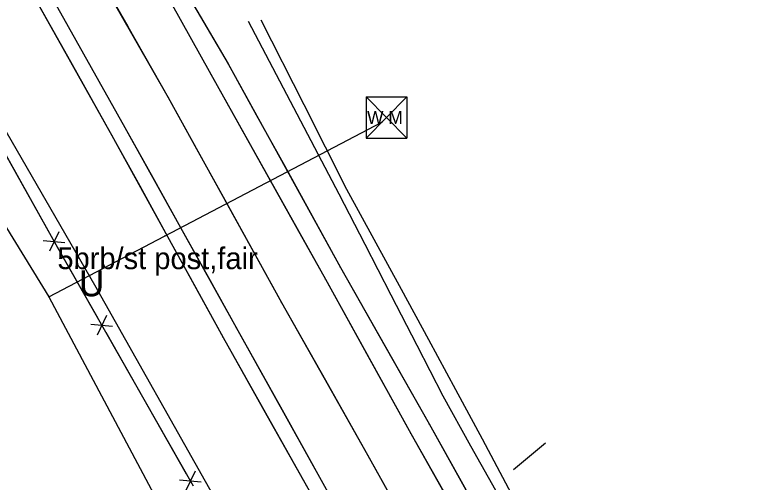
# Model space of a CAD drawing. Extents: x -99999 to 591807, y -99999 to 347168.
# Drawn here: x 589017.5 to 589188.3, y 344083.1 to 344190.7 of the extents above; entities that cross this region are included whole.
import ezdxf

# ---------------------------------------------------------------- set-up
doc = ezdxf.new("R2010")
doc.units = 0
for name, color, linetype in [('S_DITCHLINE', 7, 'Continuous'), ('S_EDGE_PAVEMENT', 7, 'Continuous'), ('S_FENCE', 7, 'Continuous'), ('S_FENCE_ANNOT', 7, 'Continuous'), ('S_MSC_PT_SYM', 7, 'Continuous'), ('S_PAVEMENT_CROWN', 7, 'Continuous'), ('S_RDW_PT_SYM', 7, 'Continuous'), ('S_SHOULDER', 7, 'Continuous'), ('S_UNDERGROUND_CABLE', 7, 'Continuous'), ('S_UTL_PT_SYM', 7, 'Continuous'), ('S_WATER_UTILITIES', 7, 'Continuous')]:
    doc.layers.add(name, color=color, linetype=linetype)

msp = doc.modelspace()

# ---------------------------------------------------------------- linework, layer by layer
at = {"layer": 'S_DITCHLINE'}
for points in [[(589071.18, 344189.2), (589081.62, 344169.35), (589092.05, 344149.49), (589098.03, 344137.86), (589104.01, 344126.23), (589109.98, 344114.6), (589115.96, 344102.97), (589122.36, 344091.49), (589128.76, 344080.01), (589135.52, 344066.08), (589142.28, 344052.16)], [(589074.12, 344189.54), (589083.99, 344170.05), (589093.86, 344150.55), (589100.13, 344139.02), (589106.4, 344127.49), (589112.67, 344115.96), (589118.94, 344104.44), (589125.03, 344093.05), (589131.12, 344081.67), (589138.87, 344067.77), (589146.61, 344053.87)], [(589132.23, 344086.04), (589139.62, 344092.13)]]:
    msp.add_lwpolyline(points, dxfattribs=at)
at = {"layer": 'S_EDGE_PAVEMENT'}
for points in [[(589044.06, 344210.38), (589062.61, 344176.98), (589089.04, 344129.8), (589108.67, 344094.28), (589125.56, 344064.19), (589145.2, 344028.97), (589161.69, 343999.91), (589175.36, 343974.71), (589194.37, 343940.44), (589208.05, 343916.06), (589231.37, 343874.53), (589249.48, 343841.72), (589270.08, 343805.14), (589289.8, 343769.16), (589308.91, 343733.9), (589328.84, 343697.75)], [(589023.86, 344198.7), (589042.88, 344164.72), (589068.45, 344118.72), (589088.8, 344082.18), (589106.8, 344049.99), (589124.92, 344017.73), (589142.03, 343987.05), (589155.39, 343963.21), (589174.41, 343928.82), (589188.27, 343903.72), (589210.34, 343864.33), (589229.44, 343830.56), (589250.2, 343793.38), (589269.11, 343758.95), (589288.96, 343722.64), (589307.86, 343688.02)], [(589023.86, 344198.7), (589033.37, 344181.71), (589042.88, 344164.72), (589049.27, 344153.22), (589055.66, 344141.72), (589062.06, 344130.22), (589068.45, 344118.72), (589078.62, 344100.45), (589088.8, 344082.18), (589097.8, 344066.09), (589106.8, 344049.99), (589115.86, 344033.86), (589124.92, 344017.73), (589133.47, 344002.39), (589142.03, 343987.05), (589148.71, 343975.13), (589155.39, 343963.21)], [(589053.34, 344193.68), (589062.61, 344176.98), (589069.22, 344165.18), (589075.82, 344153.39), (589082.43, 344141.59), (589089.04, 344129.8), (589098.85, 344112.04), (589108.67, 344094.28), (589117.12, 344079.24), (589125.56, 344064.19), (589135.38, 344046.58), (589145.2, 344028.97), (589153.44, 344014.44), (589161.69, 343999.91), (589168.52, 343987.31), (589175.36, 343974.71), (589184.86, 343957.58)]]:
    msp.add_lwpolyline(points, dxfattribs=at)
at = {"layer": 'S_FENCE'}
for p, q in [((588991.55, 344201.14), (589027.33, 344137.13)), ((589027.66, 344140.75), (589025.49, 344136.24)), ((589024.09, 344138.75), (589029.06, 344138.24)), ((589027.33, 344137.13), (589058.59, 344082.25)), ((589038.6, 344121.49), (589036.46, 344116.97)), ((589035.04, 344119.46), (589040.02, 344118.99)), ((589058.99, 344085.67), (589056.85, 344081.15)), ((589055.43, 344083.65), (589060.41, 344083.18))]:
    msp.add_line(p, q, dxfattribs=at)
for points in [[(589004.28, 344178.36), (589025.51, 344140.39)], [(589027.33, 344137.13), (589036.6, 344120.86)], [(589038.46, 344117.6), (589056.99, 344085.04)]]:
    msp.add_lwpolyline(points, dxfattribs=at)
at = {"layer": 'S_MSC_PT_SYM'}
msp.add_lwpolyline([(589027.33, 344137.13), (589027.33, 344137.18), (589027.33, 344137.13), (589027.28, 344137.13), (589027.33, 344137.13), (589027.33, 344137.08), (589027.33, 344137.13), (589027.38, 344137.13)], dxfattribs=at)
at = {"layer": 'S_PAVEMENT_CROWN'}
for points in [[(589034.18, 344204.28), (589052.82, 344171.66), (589078.89, 344124.45), (589099.08, 344088.67), (589116.35, 344057.6), (589135.37, 344023.69), (589152.41, 343993.38), (589165.9, 343969), (589184.66, 343935.23), (589198.39, 343910.2), (589220.86, 343870.52), (589240.04, 343836.28), (589260.16, 343799.88), (589280.05, 343763.84), (589299.46, 343728.43), (589318.91, 343692.89)], [(589034.18, 344204.28), (589043.5, 344187.97), (589052.82, 344171.66), (589059.34, 344159.86), (589065.85, 344148.06), (589072.37, 344136.25), (589078.89, 344124.45), (589088.99, 344106.56), (589099.08, 344088.67), (589107.72, 344073.14), (589116.35, 344057.6), (589125.86, 344040.65), (589135.37, 344023.69), (589143.89, 344008.53), (589152.41, 343993.38), (589159.15, 343981.19), (589165.9, 343969), (589175.28, 343952.11)]]:
    msp.add_lwpolyline(points, dxfattribs=at)
at = {"layer": 'S_RDW_PT_SYM'}
for points in [[(589066.61, 344179.41), (589066.65, 344179.44), (589066.61, 344179.41), (589066.58, 344179.46), (589066.61, 344179.41), (589066.56, 344179.39), (589066.61, 344179.41), (589066.63, 344179.37)], [(589062.61, 344176.98), (589062.65, 344177), (589062.61, 344176.98), (589062.59, 344177.02), (589062.61, 344176.98), (589062.57, 344176.95), (589062.61, 344176.98), (589062.64, 344176.93)], [(589052.82, 344171.66), (589052.86, 344171.69), (589052.82, 344171.66), (589052.8, 344171.71), (589052.82, 344171.66), (589052.78, 344171.64), (589052.82, 344171.66), (589052.84, 344171.62)], [(589042.88, 344164.72), (589042.92, 344164.75), (589042.88, 344164.72), (589042.85, 344164.77), (589042.88, 344164.72), (589042.83, 344164.7), (589042.88, 344164.72), (589042.9, 344164.68)], [(589039.88, 344162.93), (589039.93, 344162.95), (589039.88, 344162.93), (589039.86, 344162.97), (589039.88, 344162.93), (589039.84, 344162.9), (589039.88, 344162.93), (589039.91, 344162.88)], [(589092.47, 344132.5), (589092.52, 344132.52), (589092.47, 344132.5), (589092.45, 344132.54), (589092.47, 344132.5), (589092.43, 344132.47), (589092.47, 344132.5), (589092.5, 344132.45)], [(589089.04, 344129.8), (589089.08, 344129.82), (589089.04, 344129.8), (589089.01, 344129.84), (589089.04, 344129.8), (589088.99, 344129.77), (589089.04, 344129.8), (589089.06, 344129.75)], [(589078.89, 344124.45), (589078.93, 344124.47), (589078.89, 344124.45), (589078.86, 344124.49), (589078.89, 344124.45), (589078.84, 344124.42), (589078.89, 344124.45), (589078.91, 344124.41)], [(589068.45, 344118.72), (589068.49, 344118.74), (589068.45, 344118.72), (589068.43, 344118.76), (589068.45, 344118.72), (589068.41, 344118.7), (589068.45, 344118.72), (589068.48, 344118.68)], [(589065.49, 344116.38), (589065.54, 344116.41), (589065.49, 344116.38), (589065.47, 344116.43), (589065.49, 344116.38), (589065.45, 344116.36), (589065.49, 344116.38), (589065.52, 344116.34)], [(589112.82, 344096.51), (589112.86, 344096.53), (589112.82, 344096.51), (589112.79, 344096.55), (589112.82, 344096.51), (589112.77, 344096.48), (589112.82, 344096.51), (589112.84, 344096.46)], [(589108.67, 344094.28), (589108.71, 344094.3), (589108.67, 344094.28), (589108.65, 344094.32), (589108.67, 344094.28), (589108.63, 344094.25), (589108.67, 344094.28), (589108.69, 344094.23)], [(589099.08, 344088.67), (589099.13, 344088.69), (589099.08, 344088.67), (589099.06, 344088.71), (589099.08, 344088.67), (589099.04, 344088.64), (589099.08, 344088.67), (589099.11, 344088.62)]]:
    msp.add_lwpolyline(points, close=True, dxfattribs=at)
at = {"layer": 'S_SHOULDER'}
for points in [[(588738.19, 344865.87), (588742.81, 344841.87), (588751.14, 344801.34), (588761.84, 344755.05), (588772.68, 344713.58), (588786.05, 344670.32), (588798.82, 344633.99), (588814.89, 344593.26), (588835.93, 344543.63), (588857.06, 344499.35), (588874.94, 344464.7), (588894.38, 344427.63), (588918.68, 344382.54), (588937.74, 344348.11), (588959.08, 344307.72), (588979.45, 344271.19), (588999.32, 344234.44), (589020.87, 344196.88), (589039.88, 344162.93), (589065.49, 344116.38), (589085.6, 344080.47), (589103.48, 344047.79), (589120.92, 344015.14), (589133.17, 343992.99)], [(588783.95, 344805.76), (588792.82, 344762.54), (588803.1, 344724.26), (588816.56, 344680.32), (588829.98, 344641.87), (588844.53, 344604.38), (588864.68, 344556.8), (588885.33, 344514.26), (588902.84, 344478.66), (588922.04, 344442.41), (588946.39, 344397.88), (588965.14, 344362.58), (588986.97, 344322.29), (589005.45, 344284.66), (589025.19, 344249.51), (589047.29, 344212.37), (589066.61, 344179.41), (589092.47, 344132.5), (589112.82, 344096.51), (589129.8, 344066.12), (589149.16, 344031.26), (589168.63, 343996.79)], [(589020.87, 344196.88), (589030.38, 344179.9), (589039.88, 344162.93), (589046.29, 344151.29), (589052.69, 344139.66), (589059.09, 344128.02), (589065.49, 344116.38), (589075.54, 344098.43), (589085.6, 344080.47), (589094.54, 344064.13), (589103.48, 344047.79), (589112.2, 344031.47), (589120.92, 344015.14), (589127.04, 344004.07), (589133.17, 343992.99)], [(589056.95, 344195.89), (589066.61, 344179.41), (589073.07, 344167.68), (589079.54, 344155.95), (589086.01, 344144.23), (589092.47, 344132.5), (589102.65, 344114.5), (589112.82, 344096.51), (589121.31, 344081.32), (589129.8, 344066.12), (589139.48, 344048.69), (589149.16, 344031.26), (589158.9, 344014.02), (589168.63, 343996.79)]]:
    msp.add_lwpolyline(points, dxfattribs=at)
at = {"layer": 'S_UNDERGROUND_CABLE'}
for p, q in [((589035.95, 344128.43), (588982.03, 344221.78)), ((589095.48, 344022.97), (589035.95, 344128.43))]:
    msp.add_line(p, q, dxfattribs=at)
at = {"layer": 'S_UTL_PT_SYM'}
for points in [[(589101.96, 344165.94), (589101.96, 344165.99), (589101.96, 344165.94), (589101.91, 344165.94), (589101.96, 344165.94), (589101.96, 344165.89), (589101.96, 344165.94), (589102.01, 344165.94)], [(589051.94, 344139.71), (589051.94, 344139.76), (589051.94, 344139.71), (589051.89, 344139.71), (589051.94, 344139.71), (589051.94, 344139.66), (589051.94, 344139.71), (589051.99, 344139.71)], [(589025.34, 344125.78), (589025.34, 344125.83), (589025.34, 344125.78), (589025.29, 344125.78), (589025.34, 344125.78), (589025.34, 344125.73), (589025.34, 344125.78), (589025.39, 344125.78)], [(589025.35, 344125.79), (589025.35, 344125.84), (589025.35, 344125.79), (589025.3, 344125.79), (589025.35, 344125.79), (589025.35, 344125.74), (589025.35, 344125.79), (589025.4, 344125.79)]]:
    msp.add_lwpolyline(points, dxfattribs=at)
at = {"layer": 'S_WATER_UTILITIES'}
for p, q in [((589098.36, 344171.78), (589107.7, 344171.78)), ((589098.36, 344171.78), (589098.36, 344162.29)), ((589098.36, 344171.78), (589107.7, 344162.29)), ((589107.7, 344171.78), (589098.36, 344162.29)), ((589107.7, 344171.78), (589107.7, 344162.29)), ((589051.94, 344139.71), (589101.96, 344165.94)), ((589003.01, 344162.15), (589025.35, 344125.79)), ((589098.36, 344162.29), (589107.7, 344162.29)), ((589025.34, 344125.78), (589051.94, 344139.71)), ((589025.35, 344125.79), (589102.43, 343980.76))]:
    msp.add_line(p, q, dxfattribs=at)

# ---------------------------------------------------------------- texts
at = {"layer": 'S_FENCE_ANNOT'}
msp.add_text('5brb/st post,fair', height=5, dxfattribs=at).set_placement((589027.33, 344132.13))
at = {"layer": 'S_UTL_PT_SYM'}
msp.add_text('U', height=6, rotation=360, dxfattribs=at).set_placement((589032.32, 344125.88))
at = {"layer": 'S_WATER_UTILITIES'}
msp.add_text('W M', height=3, rotation=360, dxfattribs=at).set_placement((589098.56, 344165.55))

doc.saveas('drawing.dxf')
